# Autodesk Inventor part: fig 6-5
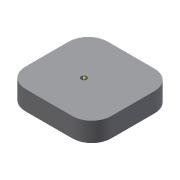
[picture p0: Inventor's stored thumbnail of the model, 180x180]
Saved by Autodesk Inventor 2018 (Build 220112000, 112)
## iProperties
Created: 2004-05
Part Number: fig 6-5
Document SubType Name: Modeling
Designer: CADCIM Technologies
Manufacturer: Standard
Standards Organization: Custom
Density: 1 g/cm^3
Material: Generic
Appearance: Default
Author: CADCIM Technologies
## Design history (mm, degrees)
sketch "Sketch1"
  geometry: L1 (0, 0)-(44.293, 0); L2 (44.293, 0)-(44.293, 42.442); L3 (44.293, 42.442)-(0, 42.442); L4 (0, 42.442)-(0, 0)
  constraints: 8 end point, 2 parallel, 1 horizontal, 1 perpendicular
extrude "Extrusion1" new body sketch "Sketch1" distance "d0" = 10; taper "d1" = 0 deg
fillet "Fillet1" dims "d2" = 10
sketch "Sketch2"
  geometry: 1 further point
sketch "Sketch3"
  geometry: L1 (10, 42.442)-(34.293, 42.442) reference; L2 (0, 10)-(0, 32.442) reference; L3 (34.293, 0)-(10, 0) reference; L4 (44.293, 32.442)-(44.293, 10) reference; A1 r 10 centre (34.293, 32.442) between (44.293, 32.442) and (34.293, 42.442) reference; A2 r 10 centre (10, 32.442) between (10, 42.442) and (0, 32.442) reference; A3 r 10 centre (10, 10) between (0, 10) and (10, 0) reference; A4 r 10 centre (34.293, 10) between (34.293, 0) and (44.293, 10) reference; 1 further point
workaxis "Work Axis1"
  workpoint "Work Point1"
hole "Hole3" diameter "d24" = 3; stored, may be unused: countersink angle "d28" = 90 deg, drill point angle "d30" = 118 deg; dims "d22" = 10, "d23" = 10, "d25" = 6, "d26" = 4, "d27" = 2, "d29" = 8
body "Solid1"
